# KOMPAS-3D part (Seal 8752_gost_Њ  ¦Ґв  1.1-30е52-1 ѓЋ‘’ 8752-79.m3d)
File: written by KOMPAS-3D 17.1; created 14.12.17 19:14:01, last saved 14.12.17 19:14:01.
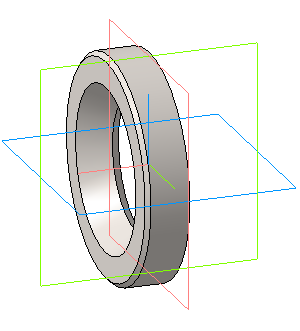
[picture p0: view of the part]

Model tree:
1. Операция без истории:1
